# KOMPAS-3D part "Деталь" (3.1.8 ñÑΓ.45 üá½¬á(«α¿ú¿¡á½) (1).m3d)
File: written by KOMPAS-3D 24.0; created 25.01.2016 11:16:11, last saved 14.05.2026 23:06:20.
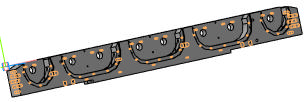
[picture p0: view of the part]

Document properties: Полное имя файла: E:\test_kompas\all_v22\3.1.8 дет.45 Балка(оригинал) (1).m3d

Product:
- Part/product: Деталь
    Масса: 261.985445

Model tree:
1. Эскиз:1
2. Операция выдавливания:1
     Расстояние 1 = 115
3. Эскиз:9  (with: Грань.Операция выдавливания:1, Ребро.Операция выдавливания:1)
4. Вырезать элемент выдавливания:13
     Расстояние 1 = 115
5. Эскиз:19  (with: Грань.Операция выдавливания:1)
6. Вырезать элемент выдавливания:14
     Расстояние 1 = 231
7. Эскиз:20  (with: Грань.Операция выдавливания:1, Ребро.Операция выдавливания:1)
8. Эскиз:21  (with: Грань.Операция выдавливания:1)
9. Вырезать элемент выдавливания:15
     Расстояние 1 = 75
10. Вырезать элемент выдавливания:16
     Расстояние 1 = 10
11. Эскиз:22  (with: Грань.Операция выдавливания:1, Ребро.Операция выдавливания:1, Ребро.Вырезать элемент выдавливания:14)
12. Вырезать элемент выдавливания:17
     Расстояние 1 = 30
13. Эскиз:23  (with: Грань.Операция выдавливания:1)
14. Вырезать элемент выдавливания:18
     Расстояние 1 = 30
15. Условное изображение резьбы:1  (with: Ребро.Вырезать элемент выдавливания:17, Грань.Вырезать элемент выдавливания:17)
     Длина резьбы = 30; Шаг резьбы = 2; Номинальный диаметр резьбы = 20.0651
16. Условное изображение резьбы:2  (with: Ребро.Вырезать элемент выдавливания:17, Грань.Вырезать элемент выдавливания:17)
     Длина резьбы = 30; Шаг резьбы = 2; Номинальный диаметр резьбы = 20.0651
17. Условное изображение резьбы:3  (with: Ребро.Вырезать элемент выдавливания:18, Грань.Вырезать элемент выдавливания:18)
     Длина резьбы = 30; Шаг резьбы = 2; Номинальный диаметр резьбы = 20.0651
18. Условное изображение резьбы:4  (with: Ребро.Вырезать элемент выдавливания:18, Грань.Вырезать элемент выдавливания:18)
     Длина резьбы = 30; Шаг резьбы = 2; Номинальный диаметр резьбы = 20.0651
19. Эскиз:24  (with: Грань.Операция выдавливания:1)
20. Вырезать элемент выдавливания:19
     Расстояние 1 = 75
21. Эскиз:25  (with: Грань.Операция выдавливания:1, Ребро.Операция выдавливания:1)
22. Вырезать элемент выдавливания:20
     Расстояние 1 = 35
23. Условное изображение резьбы:5  (with: Ребро.Вырезать элемент выдавливания:20, Грань.Вырезать элемент выдавливания:20)
     Длина резьбы = 35; Шаг резьбы = 1.5; Номинальный диаметр резьбы = 20.0538
24. Условное изображение резьбы:6  (with: Ребро.Вырезать элемент выдавливания:20, Грань.Вырезать элемент выдавливания:20)
     Длина резьбы = 35; Шаг резьбы = 1.5; Номинальный диаметр резьбы = 20.0538
25. Условное изображение резьбы:7  (with: Ребро.Вырезать элемент выдавливания:20, Грань.Вырезать элемент выдавливания:20)
     Длина резьбы = 35; Шаг резьбы = 1.5; Номинальный диаметр резьбы = 20.0538
26. Условное изображение резьбы:8  (with: Ребро.Вырезать элемент выдавливания:20, Грань.Вырезать элемент выдавливания:20)
     Длина резьбы = 35; Шаг резьбы = 1.5; Номинальный диаметр резьбы = 20.0538
27. Условное изображение резьбы:9  (with: Ребро.Вырезать элемент выдавливания:20, Грань.Вырезать элемент выдавливания:20)
     Длина резьбы = 35; Шаг резьбы = 1; Номинальный диаметр резьбы = 19.5125
28. Условное изображение резьбы:10  (with: Ребро.Вырезать элемент выдавливания:20, Грань.Вырезать элемент выдавливания:20)
     Длина резьбы = 35; Шаг резьбы = 1; Номинальный диаметр резьбы = 19.5125
29. Эскиз:26  (with: Грань.Операция выдавливания:1, Ребро.Операция выдавливания:1, Ребро.Вырезать элемент выдавливания:13)
30. Вырезать элемент выдавливания:21
     Расстояние 1 = 35
31. Условное изображение резьбы:11  (with: Ребро.Вырезать элемент выдавливания:21, Грань.Вырезать элемент выдавливания:21)
     Длина резьбы = 35; Шаг резьбы = 1.5; Номинальный диаметр резьбы = 20.0538
32. Условное изображение резьбы:12  (with: Ребро.Вырезать элемент выдавливания:21, Грань.Вырезать элемент выдавливания:21)
     Длина резьбы = 35; Шаг резьбы = 1.5; Номинальный диаметр резьбы = 20.0538
33. Условное изображение резьбы:13  (with: Ребро.Вырезать элемент выдавливания:21, Грань.Вырезать элемент выдавливания:21)
     Длина резьбы = 35; Шаг резьбы = 1.5; Номинальный диаметр резьбы = 20.0538
34. Условное изображение резьбы:14  (with: Ребро.Вырезать элемент выдавливания:21, Грань.Вырезать элемент выдавливания:21)
     Длина резьбы = 35; Шаг резьбы = 1.5; Номинальный диаметр резьбы = 20.0538
35. Условное изображение резьбы:15  (with: Ребро.Вырезать элемент выдавливания:21, Грань.Вырезать элемент выдавливания:21)
     Длина резьбы = 35; Шаг резьбы = 1.5; Номинальный диаметр резьбы = 20.0538
36. Условное изображение резьбы:16  (with: Ребро.Вырезать элемент выдавливания:21, Грань.Вырезать элемент выдавливания:21)
     Длина резьбы = 35; Шаг резьбы = 1.5; Номинальный диаметр резьбы = 20.0538
37. Эскиз:27  (with: Грань.Операция выдавливания:1, Ребро.Операция выдавливания:1, Ребро.Вырезать элемент выдавливания:15)
38. Эскиз:28  (with: Грань.Операция выдавливания:1)
39. Вырезать элемент выдавливания:22
     Расстояние 1 = 115
40. Эскиз:29  (with: Грань.Вырезать элемент выдавливания:16, Ребро.Вырезать элемент выдавливания:16)
41. Вырезать элемент выдавливания:23
     Расстояние 1 = 13
42. Эскиз:30  (with: Грань.Вырезать элемент выдавливания:16)
43. Вырезать элемент выдавливания:24
     Расстояние 1 = 13
44. Условное изображение резьбы:17  (with: Ребро.Вырезать элемент выдавливания:23, Грань.Вырезать элемент выдавливания:23)
     Длина резьбы = 13; Шаг резьбы = 1; Номинальный диаметр резьбы = 9.51253
45. Условное изображение резьбы:18  (with: Ребро.Вырезать элемент выдавливания:23, Грань.Вырезать элемент выдавливания:23)
     Длина резьбы = 13; Шаг резьбы = 1; Номинальный диаметр резьбы = 9.51253
46. Условное изображение резьбы:19  (with: Ребро.Вырезать элемент выдавливания:23, Грань.Вырезать элемент выдавливания:23)
     Длина резьбы = 13; Шаг резьбы = 1; Номинальный диаметр резьбы = 9.51253
47. Условное изображение резьбы:20  (with: Ребро.Вырезать элемент выдавливания:23, Грань.Вырезать элемент выдавливания:23)
     Длина резьбы = 13; Шаг резьбы = 1; Номинальный диаметр резьбы = 9.51253
48. Условное изображение резьбы:21  (with: Ребро.Вырезать элемент выдавливания:23, Грань.Вырезать элемент выдавливания:23)
     Длина резьбы = 13; Шаг резьбы = 1; Номинальный диаметр резьбы = 9.51253
49. Условное изображение резьбы:22  (with: Ребро.Вырезать элемент выдавливания:24, Грань.Вырезать элемент выдавливания:24)
     Длина резьбы = 13; Шаг резьбы = 1; Номинальный диаметр резьбы = 9.51253
50. Условное изображение резьбы:23  (with: Ребро.Вырезать элемент выдавливания:24, Грань.Вырезать элемент выдавливания:24)
     Длина резьбы = 13; Шаг резьбы = 1; Номинальный диаметр резьбы = 9.51253
51. Условное изображение резьбы:24  (with: Ребро.Вырезать элемент выдавливания:24, Грань.Вырезать элемент выдавливания:24)
     Длина резьбы = 13; Шаг резьбы = 1; Номинальный диаметр резьбы = 9.51253
52. Условное изображение резьбы:25  (with: Ребро.Вырезать элемент выдавливания:24, Грань.Вырезать элемент выдавливания:24)
     Длина резьбы = 13; Шаг резьбы = 1; Номинальный диаметр резьбы = 9.51253
53. Условное изображение резьбы:26  (with: Ребро.Вырезать элемент выдавливания:24, Грань.Вырезать элемент выдавливания:24)
     Длина резьбы = 13; Шаг резьбы = 1; Номинальный диаметр резьбы = 9.51253
54. Эскиз:31  (with: Грань.Вырезать элемент выдавливания:16, Ребро.Вырезать элемент выдавливания:16, Ребро.Вырезать элемент выдавливания:19)
55. Вырезать элемент выдавливания:25
     Расстояние 1 = 13
56. Условное изображение резьбы:27  (with: Ребро.Вырезать элемент выдавливания:25, Грань.Вырезать элемент выдавливания:25)
     Длина резьбы = 13; Шаг резьбы = 1; Номинальный диаметр резьбы = 9.51253
57. Условное изображение резьбы:28  (with: Ребро.Вырезать элемент выдавливания:25, Грань.Вырезать элемент выдавливания:25)
     Длина резьбы = 13; Шаг резьбы = 1; Номинальный диаметр резьбы = 9.51253
58. Условное изображение резьбы:29  (with: Ребро.Вырезать элемент выдавливания:25, Грань.Вырезать элемент выдавливания:25)
     Длина резьбы = 13; Шаг резьбы = 1; Номинальный диаметр резьбы = 9.51253
59. Условное изображение резьбы:30  (with: Ребро.Вырезать элемент выдавливания:25, Грань.Вырезать элемент выдавливания:25)
     Длина резьбы = 13; Шаг резьбы = 1; Номинальный диаметр резьбы = 9.51253
60. Условное изображение резьбы:31  (with: Ребро.Вырезать элемент выдавливания:25, Грань.Вырезать элемент выдавливания:25)
     Длина резьбы = 13; Шаг резьбы = 1; Номинальный диаметр резьбы = 9.51253
61. Условное изображение резьбы:32  (with: Ребро.Вырезать элемент выдавливания:25, Грань.Вырезать элемент выдавливания:25)
     Длина резьбы = 13; Шаг резьбы = 1; Номинальный диаметр резьбы = 9.51253
62. Условное изображение резьбы:33  (with: Ребро.Вырезать элемент выдавливания:25, Грань.Вырезать элемент выдавливания:25)
     Длина резьбы = 13; Шаг резьбы = 1; Номинальный диаметр резьбы = 9.51253
63. Эскиз:32  (with: Грань.Вырезать элемент выдавливания:16)
64. Вырезать элемент выдавливания:26
     Расстояние 1 = 13
65. Условное изображение резьбы:34  (with: Ребро.Вырезать элемент выдавливания:26, Грань.Вырезать элемент выдавливания:26)
     Длина резьбы = 13; Шаг резьбы = 1; Номинальный диаметр резьбы = 9.51253
66. Условное изображение резьбы:35  (with: Ребро.Вырезать элемент выдавливания:26, Грань.Вырезать элемент выдавливания:26)
     Длина резьбы = 13; Шаг резьбы = 1; Номинальный диаметр резьбы = 9.51253
67. Условное изображение резьбы:36  (with: Ребро.Вырезать элемент выдавливания:26, Грань.Вырезать элемент выдавливания:26)
     Длина резьбы = 13; Шаг резьбы = 1; Номинальный диаметр резьбы = 9.51253
68. Условное изображение резьбы:37  (with: Ребро.Вырезать элемент выдавливания:26, Грань.Вырезать элемент выдавливания:26)
     Длина резьбы = 13; Шаг резьбы = 1; Номинальный диаметр резьбы = 9.51253
69. Условное изображение резьбы:38  (with: Ребро.Вырезать элемент выдавливания:26, Грань.Вырезать элемент выдавливания:26)
     Длина резьбы = 13; Шаг резьбы = 1; Номинальный диаметр резьбы = 9.51253
70. Условное изображение резьбы:39  (with: Ребро.Вырезать элемент выдавливания:26, Грань.Вырезать элемент выдавливания:26)
     Длина резьбы = 13; Шаг резьбы = 1; Номинальный диаметр резьбы = 9.51253
71. Условное изображение резьбы:40  (with: Ребро.Вырезать элемент выдавливания:26, Грань.Вырезать элемент выдавливания:26)
     Длина резьбы = 13; Шаг резьбы = 1; Номинальный диаметр резьбы = 9.51253
72. Эскиз:33  (with: Грань.Вырезать элемент выдавливания:16, Ребро.Вырезать элемент выдавливания:16)
73. Вырезать элемент выдавливания:27
     Расстояние 1 = 13
74. Условное изображение резьбы:41  (with: Ребро.Вырезать элемент выдавливания:27, Грань.Вырезать элемент выдавливания:27)
     Длина резьбы = 13; Шаг резьбы = 1; Номинальный диаметр резьбы = 9.51253
75. Условное изображение резьбы:42  (with: Ребро.Вырезать элемент выдавливания:27, Грань.Вырезать элемент выдавливания:27)
     Длина резьбы = 13; Шаг резьбы = 1; Номинальный диаметр резьбы = 9.51253
76. Условное изображение резьбы:43  (with: Ребро.Вырезать элемент выдавливания:27, Грань.Вырезать элемент выдавливания:27)
     Длина резьбы = 13; Шаг резьбы = 1; Номинальный диаметр резьбы = 9.51253
77. Условное изображение резьбы:44  (with: Ребро.Вырезать элемент выдавливания:27, Грань.Вырезать элемент выдавливания:27)
     Длина резьбы = 13; Шаг резьбы = 1; Номинальный диаметр резьбы = 9.51253
78. Условное изображение резьбы:45  (with: Ребро.Вырезать элемент выдавливания:27, Грань.Вырезать элемент выдавливания:27)
     Длина резьбы = 13; Шаг резьбы = 1; Номинальный диаметр резьбы = 9.51253
79. Условное изображение резьбы:46  (with: Ребро.Вырезать элемент выдавливания:27, Грань.Вырезать элемент выдавливания:27)
     Длина резьбы = 13; Шаг резьбы = 1; Номинальный диаметр резьбы = 9.51253
80. Условное изображение резьбы:47  (with: Ребро.Вырезать элемент выдавливания:27, Грань.Вырезать элемент выдавливания:27)
     Длина резьбы = 13; Шаг резьбы = 1; Номинальный диаметр резьбы = 9.51253
81. Эскиз:34  (with: Грань.Операция выдавливания:1, Ребро.Операция выдавливания:1)
82. Эскиз:35  (with: Грань.Операция выдавливания:1, Ребро.Операция выдавливания:1, Ребро.Вырезать элемент выдавливания:17)
83. Вырезать элемент выдавливания:28
     Расстояние 1 = 94
84. Эскиз:36  (with: Грань.Операция выдавливания:1, Ребро.Операция выдавливания:1)
85. Вырезать элемент выдавливания:29
     Расстояние 1 = 21
86. Эскиз:37  (with: Грань.Вырезать элемент выдавливания:15, Ребро.Вырезать элемент выдавливания:15)
87. Вырезать элемент выдавливания:30
     Расстояние 1 = 40
88. Эскиз:38  (with: Грань.Операция выдавливания:1, Ребро.Операция выдавливания:1)
89. Вырезать элемент выдавливания:31
     Расстояние 1 = 10
90. Эскиз:39  (with: Грань.Операция выдавливания:1, Ребро.Операция выдавливания:1)
91. Вырезать элемент выдавливания:32
     Расстояние 1 = 50
92. Условное изображение резьбы:48  (with: Ребро.Вырезать элемент выдавливания:32, Грань.Вырезать элемент выдавливания:32)
     Длина резьбы = 50; Шаг резьбы = 1; Номинальный диаметр резьбы = 18.0325
93. Условное изображение резьбы:49  (with: Ребро.Вырезать элемент выдавливания:32, Грань.Вырезать элемент выдавливания:32)
     Длина резьбы = 50; Шаг резьбы = 1; Номинальный диаметр резьбы = 18.0325
94. Условное изображение резьбы:50  (with: Ребро.Вырезать элемент выдавливания:32, Грань.Вырезать элемент выдавливания:32)
     Длина резьбы = 50; Шаг резьбы = 1; Номинальный диаметр резьбы = 18.0325
95. Условное изображение резьбы:51  (with: Ребро.Вырезать элемент выдавливания:32, Грань.Вырезать элемент выдавливания:32)
     Длина резьбы = 50; Шаг резьбы = 1; Номинальный диаметр резьбы = 18.0325
96. Эскиз:40  (with: Грань.Операция выдавливания:1, Ребро.Операция выдавливания:1, Ребро.Вырезать элемент выдавливания:13, Ребро.Вырезать элемент выдавливания:22, Ребро.Вырезать элемент выдавливания:29)
97. Вырезать элемент выдавливания:33
     Расстояние 1 = 70
98. Условное изображение резьбы:52  (with: Ребро.Вырезать элемент выдавливания:33, Грань.Вырезать элемент выдавливания:33)
     Длина резьбы = 70; Шаг резьбы = 1; Номинальный диаметр резьбы = 28.0325
99. Условное изображение резьбы:53  (with: Ребро.Вырезать элемент выдавливания:33, Грань.Вырезать элемент выдавливания:33)
     Длина резьбы = 70; Шаг резьбы = 1; Номинальный диаметр резьбы = 28.0325
100. Эскиз:41  (with: Грань.Операция выдавливания:1)
101. Вырезать элемент выдавливания:34
     Расстояние 1 = 30
102. Условное изображение резьбы:54  (with: Ребро.Вырезать элемент выдавливания:34, Грань.Вырезать элемент выдавливания:34)
     Длина резьбы = 30; Шаг резьбы = 1; Номинальный диаметр резьбы = 8.03253
103. Условное изображение резьбы:55  (with: Ребро.Вырезать элемент выдавливания:34, Грань.Вырезать элемент выдавливания:34)
     Длина резьбы = 30; Шаг резьбы = 1; Номинальный диаметр резьбы = 8.03253
104. Условное изображение резьбы:56  (with: Ребро.Вырезать элемент выдавливания:34, Грань.Вырезать элемент выдавливания:34)
     Длина резьбы = 30; Шаг резьбы = 1; Номинальный диаметр резьбы = 8.03253
105. Условное изображение резьбы:57  (with: Ребро.Вырезать элемент выдавливания:34, Грань.Вырезать элемент выдавливания:34)
     Длина резьбы = 30; Шаг резьбы = 1; Номинальный диаметр резьбы = 8.03253
106. Условное изображение резьбы:58  (with: Ребро.Вырезать элемент выдавливания:34, Грань.Вырезать элемент выдавливания:34)
     Длина резьбы = 30; Шаг резьбы = 1; Номинальный диаметр резьбы = 8.03253
107. Вырезать элемент выдавливания:35
     Расстояние 1 = 10
108. Эскиз:42  (with: Грань.Операция выдавливания:1, Ребро.Вырезать элемент выдавливания:33)
109. Вырезать элемент выдавливания:36
     Расстояние 1 = 55
110. Условное изображение резьбы:59  (with: Ребро.Вырезать элемент выдавливания:36, Грань.Вырезать элемент выдавливания:36)
     Длина резьбы = 55; Шаг резьбы = 1; Номинальный диаметр резьбы = 16.0325
111. Эскиз:43  (with: Грань.Операция выдавливания:1, Ребро.Операция выдавливания:1, Ребро.Вырезать элемент выдавливания:22)
112. Вырезать элемент выдавливания:37
     Расстояние 1 = 30
113. Условное изображение резьбы:60  (with: Ребро.Вырезать элемент выдавливания:37, Грань.Вырезать элемент выдавливания:37)
     Длина резьбы = 30; Шаг резьбы = 1; Номинальный диаметр резьбы = 11.0325
114. Условное изображение резьбы:61  (with: Ребро.Вырезать элемент выдавливания:37, Грань.Вырезать элемент выдавливания:37)
     Длина резьбы = 30; Шаг резьбы = 1; Номинальный диаметр резьбы = 11.0325
115. Условное изображение резьбы:62  (with: Ребро.Вырезать элемент выдавливания:37, Грань.Вырезать элемент выдавливания:37)
     Длина резьбы = 30; Шаг резьбы = 1; Номинальный диаметр резьбы = 11.0325
116. Условное изображение резьбы:63  (with: Ребро.Вырезать элемент выдавливания:37, Грань.Вырезать элемент выдавливания:37)
     Длина резьбы = 30; Шаг резьбы = 1; Номинальный диаметр резьбы = 11.0325
117. Условное изображение резьбы:64  (with: Ребро.Вырезать элемент выдавливания:37, Грань.Вырезать элемент выдавливания:37)
     Длина резьбы = 30; Шаг резьбы = 1; Номинальный диаметр резьбы = 11.0325
118. Условное изображение резьбы:65  (with: Ребро.Вырезать элемент выдавливания:37, Грань.Вырезать элемент выдавливания:37)
     Длина резьбы = 30; Шаг резьбы = 1; Номинальный диаметр резьбы = 11.0325
119. Условное изображение резьбы:66  (with: Ребро.Вырезать элемент выдавливания:37, Грань.Вырезать элемент выдавливания:37)
     Длина резьбы = 30; Шаг резьбы = 1; Номинальный диаметр резьбы = 11.0325
120. Условное изображение резьбы:67  (with: Ребро.Вырезать элемент выдавливания:37, Грань.Вырезать элемент выдавливания:37)
     Длина резьбы = 30; Шаг резьбы = 1; Номинальный диаметр резьбы = 11.0325
121. Условное изображение резьбы:68  (with: Ребро.Вырезать элемент выдавливания:37, Грань.Вырезать элемент выдавливания:37)
     Длина резьбы = 30; Шаг резьбы = 1; Номинальный диаметр резьбы = 11.0325
122. Условное изображение резьбы:69  (with: Ребро.Вырезать элемент выдавливания:37, Грань.Вырезать элемент выдавливания:37)
     Длина резьбы = 30; Шаг резьбы = 1; Номинальный диаметр резьбы = 11.0325
123. Условное изображение резьбы:70  (with: Ребро.Вырезать элемент выдавливания:37, Грань.Вырезать элемент выдавливания:37)
     Длина резьбы = 30; Шаг резьбы = 1; Номинальный диаметр резьбы = 11.0325
124. Условное изображение резьбы:71  (with: Ребро.Вырезать элемент выдавливания:37, Грань.Вырезать элемент выдавливания:37)
     Длина резьбы = 30; Шаг резьбы = 1; Номинальный диаметр резьбы = 11.0325
125. Условное изображение резьбы:72  (with: Ребро.Вырезать элемент выдавливания:37, Грань.Вырезать элемент выдавливания:37)
     Длина резьбы = 30; Шаг резьбы = 1; Номинальный диаметр резьбы = 11.0325
126. Условное изображение резьбы:73  (with: Ребро.Вырезать элемент выдавливания:37, Грань.Вырезать элемент выдавливания:37)
     Длина резьбы = 30; Шаг резьбы = 1; Номинальный диаметр резьбы = 11.0325
127. Условное изображение резьбы:74  (with: Ребро.Вырезать элемент выдавливания:37, Грань.Вырезать элемент выдавливания:37)
     Длина резьбы = 30; Шаг резьбы = 1; Номинальный диаметр резьбы = 11.0325
128. Условное изображение резьбы:75  (with: Ребро.Вырезать элемент выдавливания:37, Грань.Вырезать элемент выдавливания:37)  (labels: 4061045924-6285-0-0|0)
     Длина резьбы = 30; Шаг резьбы = 1; Номинальный диаметр резьбы = 11.0325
